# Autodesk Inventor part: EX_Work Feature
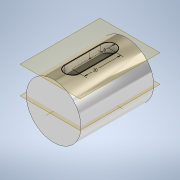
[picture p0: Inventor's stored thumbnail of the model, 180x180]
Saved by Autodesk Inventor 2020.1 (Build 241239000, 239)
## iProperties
Created: 2019-10
Part Number: EX_Work Feature
Material: Nickel-Copper Alloy 400
Document SubType Name: Modeling
Designer: Synergysoft Dell02
Density: 8.83 g/cm^3
Appearance: Chrome - Polished
Author: Synergysoft Dell02
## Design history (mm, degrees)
sketch "Sketch1"
  geometry: C1 r 15 at (0, 0); 1 further point
  constraints: 1 centre point, 1 coincident
  dimensions: "d0" = 30 diameter of C1
extrude "Extrusion1" new body sketch "Sketch1" stored distance "d1" = 40; taper "d2" = 0 deg
workplane "Work Plane1"
sketch "Sketch2"
  geometry: L1 (0, 10)-(0, -10); L2 (-4, 10)-(-4, -10); L3 (4, -10)-(4, 10); A1 r 4 centre (0, 10) between (4, 10) and (-4, 10); A2 r 4 centre (0, -10) between (-4, -10) and (4, -10); 2 further points
  constraints: 8 end point, 4 point on circle, 4 tangent, 2 centre point, 1 coincident, 1 midpoint, 1 parallel, 1 vertical
  dimensions: "d3" = 8 diameter of A2; "d4" = 20 distance of L1.start L1.end
extrude "Extrusion2" cut sketch "Sketch2" distance "d5" = 5; taper "d6" = 0 deg
body "Solid1"
